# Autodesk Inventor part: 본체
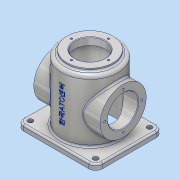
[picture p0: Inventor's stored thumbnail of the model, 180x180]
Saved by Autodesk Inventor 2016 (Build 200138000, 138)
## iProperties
Created: 2021-02
Part Number: 본체
Material: 알루미늄 6061
Document SubType Name: Modeling
Designer: user
Density: 2.7 g/cm^3
Appearance: 알루미늄 - 평지
Mass: 1235.14 g
Surface Area: 1068.45 cm^2
Volume: 457.459 cm^3
Author: user
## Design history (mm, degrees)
sketch "스케치1"
  geometry: L1 (70, 60)-(-70, 60); L2 (-70, 60)-(-70, -60); L3 (-70, -60)-(70, -60); L4 (70, -60)-(70, 60); L5 (70, 60)-(-70, -60); L6 (-70, 60)-(70, -60); 1 further point
  constraints: 12 end point, 2 midpoint, 2 parallel, 1 horizontal, 1 perpendicular
  dimensions: "d0" = 140 distance of L3.end L2.end; "d1" = 120 distance of L2.end L1.end
extrude "돌출1" new body sketch "스케치1" distance "d2" = 10; taper "d3" = 0 deg
fillet "모깎기1" dims "d4" = 12
hole "구멍1" diameter "d7" = 9; stored, may be unused: countersink angle "d11" = 90 deg, drill point angle "d13" = 118 deg; dims "d5" = 10, "d6" = 10, "d8" = 6, "d9" = 4, "d10" = 2, "d12" = 8
sketch "스케치2"
  geometry: C1 r 50 at (0, 0); 1 further point
  constraints: 1 centre point, 1 coincident
  dimensions: "d20" = 100 diameter of C1
extrude "돌출2" join sketch "스케치2" distance "d21" = 110; taper "d22" = 0 deg
sketch "스케치3"
  geometry: C1 r 41 at (0, 0); 1 further point
  constraints: 1 centre point, 1 coincident
  dimensions: "d23" = 82 diameter of C1
extrude "돌출3" join sketch "스케치3" distance "d24" = 5; taper "d25" = 0 deg
node "작업 평면1"
sketch "스케치4"
  geometry: L1 (50, 120)-(-50, 120) reference; L2 (-50, 10)-(50, 10) reference; L3 (50, 10)-(50, 120) reference; L4 (-50, 10)-(-50, 120) reference; L5 (50, 120)-(-50, 120) reference; L6 (48, 10)-(-48, 10) reference; L7 (0, 0)-(0, 60); C1 r 41 at (0, 60)
  constraints: 2 end point, 1 centre point, 1 coincident, 1 vertical
  dimensions: "d28" = 60 distance of L7.start L7.end; "d29" = 82 diameter of C1
extrude "돌출4" join sketch "스케치4" stored distance "d30" = 5; taper "d31" = 0 deg
hole "구멍2" diameter "d34" = 54; stored, may be unused: countersink angle "d38" = 90 deg, drill point angle "d40" = 118 deg; dims "d32" = 10, "d33" = 10, "d35" = 6, "d36" = 4, "d37" = 2, "d39" = 8
sketch "스케치5"
  geometry: L1 (0, 0)-(-33, 0); C1 r 27 at (0, 0) reference; C2 r 41 at (0, 0) reference; 1 further point
  constraints: 2 end point, 1 horizontal
  dimensions: "d41" = 33 distance of L1.start L1.end
hole "구멍3" sketch "스케치5" at (-33, 0) diameter "d42" = 3.459; stored, may be unused: countersink angle "d46" = 90 deg, drill point angle "d48" = 118 deg; dims "d43" = 8, "d44" = 4, "d45" = 2, "d47" = 10
hole "구멍4" diameter "d54" = 54; stored, may be unused: countersink angle "d58" = 90 deg, drill point angle "d60" = 0 deg; dims "d55" = 8, "d56" = 4, "d57" = 2, "d59" = 13, "d61" = 10, "d62" = 10
hole "구멍5" diameter "d65" = 84; stored, may be unused: countersink angle "d69" = 90 deg, drill point angle "d71" = 0 deg; dims "d66" = 8, "d67" = 4, "d68" = 2, "d70" = 10, "d102" = 10, "d103" = 10
fillet "모깎기2" dims "d72" = 3
fillet "모깎기3" dims "d73" = 6
chamfer "모따기1" distance "d74" = 1; stored, may be unused: second distance "d75" = 2, angle "d76" = 45 deg
chamfer "모따기2" distance "d77" = 1; stored, may be unused: second distance "d78" = 2, angle "d79" = 45 deg
node "작업 평면4"
sketch "스케치7"
  geometry: L1 (-58, 0)-(58, 0) reference; 3 further points
  constraints: 1 midpoint, 1 vertical alignment, 1 other
  dimensions: "d104" = 66 distance from line of L1 point (0, 66)
feature "엠보싱2" sketch "스케치7" dims "d0" = 140, "d1" = 120, "d86" = 0.5, "d87" = 0
sketch "스케치8"
  geometry: L1 (0, 0)-(0, 33); C1 r 41 at (0, 0) reference; C2 r 28 at (0, 0) reference; C3 r 28 at (0, 0) reference; 1 further point
  constraints: 2 end point, 1 vertical
  dimensions: "d88" = 33 distance of L1.start L1.end
hole "구멍6" sketch "스케치8" at (0, 33) diameter "d89" = 3.459; stored, may be unused: countersink angle "d93" = 90 deg, drill point angle "d95" = 118 deg; dims "d90" = 8, "d91" = 4, "d92" = 2, "d94" = 10
fillet "모깎기4" dims "d99" = 3
fillet "모깎기6" dims "d101" = 3
node "솔리드1"
pattern_linear "직사각형 패턴1" dims "d16" = 116, "d19" = 96
mirror "대칭1"
pattern_circular "원형 패턴1" dims angle "d50" = 360 deg
mirror "대칭2"
pattern_circular "원형 패턴2" dims angle "d97" = 360 deg
node "투영된 루프1"
node "투영된 루프2"
node "투영된 루프3"
other parameters: "d26" = 59, "d85" = 52.5
